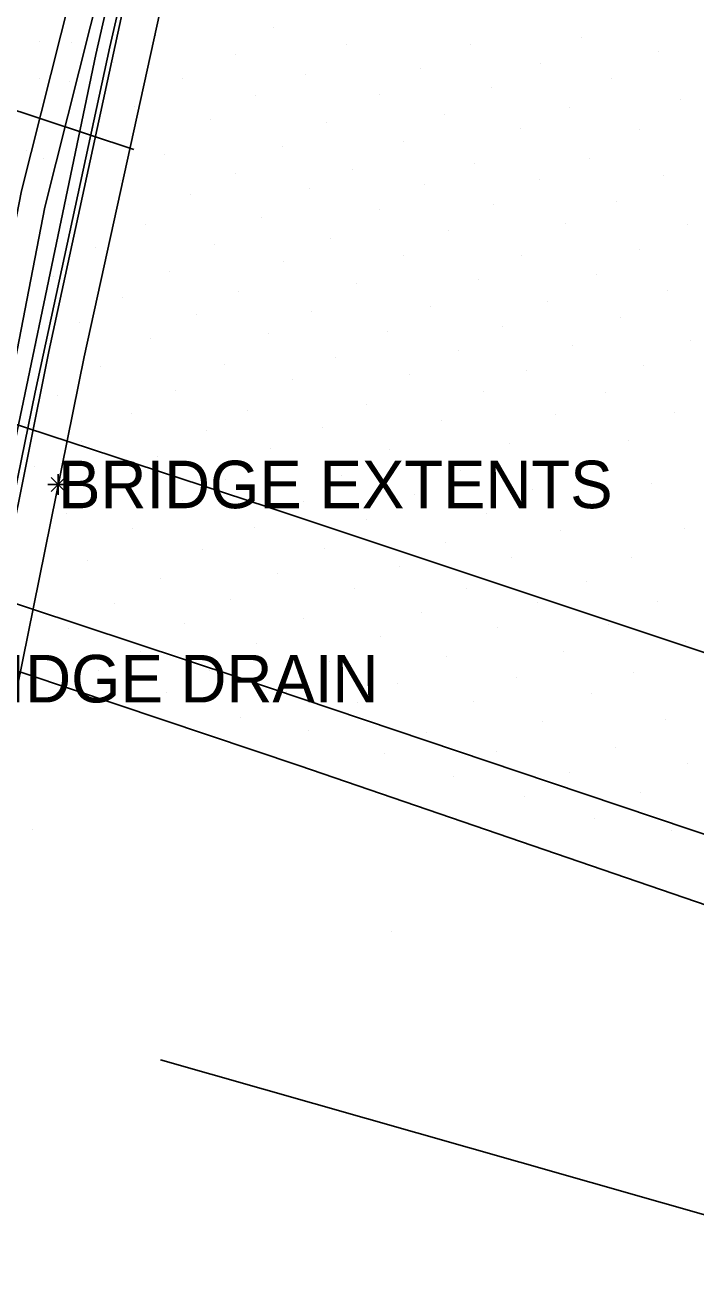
# Model space of a CAD drawing. Extents: x 1733582 to 1734070, y 467256 to 468256.
# Drawn here: x 1733868.45 to 1733893.84, y 467736.94 to 467784.83 of the extents above; entities that cross this region are included whole.
import ezdxf

# ---------------------------------------------------------------- set-up
doc = ezdxf.new("R2010")
doc.units = 0
for name, color, linetype in [('Default', 7, 'Continuous'), ('S_Bridge_Curb', 7, 'Continuous'), ('S_Bridge_Deck', 7, 'Continuous'), ('S_Bridge_Rail', 7, 'Continuous'), ('S_Ground_LevelString', 7, 'Continuous'), ('S_Ground_SpotElevation', 7, 'Continuous'), ('S_Guardrail_Beam', 7, 'Continuous'), ('S_Misc_MiscFeature', 7, 'Continuous'), ('S_Misc_MiscItems', 7, 'Continuous'), ('S_Roadway_Edge_Pavement', 7, 'Continuous'), ('S_Roadway_Painted_Lines', 7, 'Continuous'), ('S_Text', 7, 'Continuous')]:
    doc.layers.add(name, color=color, linetype=linetype)

# ---------------------------------------------------------------- blocks, each defined once
blk = doc.blocks.new('POINT_DISPLAY')
at = {"layer": 'Default'}
blk.add_line((0, 0), (0, 0), dxfattribs=at)

msp = doc.modelspace()

# ---------------------------------------------------------------- linework, layer by layer
at = {"layer": 'S_Bridge_Curb'}
msp.add_lwpolyline([(1733850.525, 467652.736), (1733851.676, 467663.636), (1733852.883, 467674.082), (1733854.262, 467685.548), (1733855.565, 467694.75), (1733856.845, 467703.748), (1733858.974, 467717.399), (1733861.233, 467731.524), (1733863.482, 467743.881), (1733865.283, 467752.922), (1733867.113, 467762.582), (1733868.83, 467770.933), (1733871.654, 467784.015), (1733874.05, 467794.414), (1733876.107, 467803.265), (1733877.952, 467810.863), (1733879.709, 467817.89), (1733881.379, 467824.23), (1733883.522, 467832.303), (1733885.6, 467839.734), (1733886.897, 467844.023)], dxfattribs=at)
at = {"layer": 'S_Bridge_Deck'}
msp.add_lwpolyline([(1733886.549, 467844.629), (1733884.683, 467838.178), (1733882.551, 467830.444), (1733878.067, 467813.135), (1733874.221, 467797.292), (1733871.125, 467783.729), (1733866.753, 467762.871), (1733863.994, 467749.165), (1733860.716, 467731.07), (1733858.373, 467716.77), (1733855.935, 467700.728), (1733853.766, 467684.771), (1733851.796, 467669.015), (1733850.46, 467656.5), (1733850.135, 467652.683), (1733850.236, 467652.213)], dxfattribs=at)
at = {"layer": 'S_Bridge_Rail'}
msp.add_lwpolyline([(1733886.303, 467841.899), (1733884.339, 467834.722), (1733880.236, 467819.247), (1733876.383, 467803.848), (1733872.741, 467788.157), (1733869.344, 467772.479), (1733866.194, 467756.807), (1733863.147, 467741.167), (1733860.402, 467725.353), (1733857.873, 467709.488), (1733855.573, 467693.7), (1733853.508, 467677.718), (1733851.616, 467661.907), (1733850.883, 467654.795)], dxfattribs=at)
at = {"layer": 'S_Ground_LevelString'}
msp.add_lwpolyline([(1733873.58, 467745.647), (1733887.182, 467741.776), (1733900.784, 467737.904), (1733914.385, 467734.032), (1733927.987, 467730.16)], dxfattribs=at)
at = {"layer": 'S_Guardrail_Beam'}
msp.add_lwpolyline([(1733971.13, 467727.753), (1733959.189, 467731.849), (1733947.467, 467735.892), (1733935.587, 467740.11), (1733923.652, 467744.12), (1733911.999, 467748.09), (1733900.23, 467752.154), (1733888.348, 467756.158), (1733876.584, 467760.123), (1733864.636, 467764.075), (1733852.71, 467768.12), (1733840.864, 467771.985), (1733828.96, 467775.911), (1733821.157, 467778.362), (1733811.276, 467781.779), (1733806.138, 467783.487), (1733804.067, 467784.255), (1733803.797, 467784.235), (1733803.622, 467784.139), (1733803.485, 467783.985), (1733803.422, 467783.75), (1733803.437, 467783.569), (1733803.561, 467783.396)], dxfattribs=at)
at = {"layer": 'S_Misc_MiscFeature'}
for points in [[(1733848.559, 467652.836), (1733852.024, 467679.791), (1733855.066, 467703.463), (1733857.598, 467722.922), (1733860.883, 467740.131), (1733863.02, 467751.281), (1733865.314, 467763.253), (1733868.31, 467778.566), (1733873.148, 467797.76), (1733879.142, 467821.53), (1733885.249, 467845.685)], [(1733849.555, 467652.651), (1733852.726, 467677.347), (1733855.925, 467702.233), (1733858.601, 467722.747), (1733863.855, 467750.228), (1733866.106, 467762.026), (1733869.19, 467777.948), (1733873.963, 467796.905), (1733880.016, 467820.978), (1733886.27, 467845.573)], [(1733887.367, 467840.604), (1733883.605, 467826.737), (1733879.636, 467811.346), (1733877.727, 467803.516), (1733874.188, 467788.265), (1733870.678, 467772.276), (1733867.49, 467756.558), (1733864.467, 467740.84), (1733861.741, 467725.141), (1733859.155, 467709.272), (1733856.917, 467693.32), (1733854.838, 467677.445), (1733853.015, 467661.799), (1733852.333, 467655.629)]]:
    msp.add_lwpolyline(points, dxfattribs=at)
at = {"layer": 'S_Misc_MiscItems'}
for p, q in [((1733869.698, 467767.836), (1733869.698, 467767.05)), ((1733870.091, 467767.443), (1733869.305, 467767.443)), ((1733869.96, 467767.181), (1733869.436, 467767.705)), ((1733869.96, 467767.705), (1733869.436, 467767.181))]:
    msp.add_line(p, q, dxfattribs=at)
at = {"layer": 'S_Roadway_Edge_Pavement'}
msp.add_lwpolyline([(1733611.876, 467844.635), (1733674.83, 467825.942), (1733744.192, 467804.366), (1733759.494, 467799.192), (1733788.268, 467787.576), (1733794.963, 467784.321), (1733814.735, 467777.995), (1733835.64, 467771.291), (1733878.809, 467756.802), (1733915.97, 467744.059), (1733950.334, 467732.351), (1733979.802, 467721.488), (1733993.679, 467716.295), (1734030.704, 467703.141), (1734054.753, 467695.101)], dxfattribs=at)
at = {"layer": 'S_Roadway_Painted_Lines'}
msp.add_line((1733858.283, 467784.833), (1733872.566, 467780.13), dxfattribs=at)
msp.add_lwpolyline([(1733613.543, 467849.189), (1733648.882, 467838.819), (1733697.382, 467824.233), (1733741.485, 467810.479), (1733805.714, 467790.022), (1733833.501, 467781.081), (1733877.654, 467766.584), (1733913.643, 467754.586), (1734001.896, 467724.119), (1734057.373, 467704.28)], dxfattribs=at)

# ---------------------------------------------------------------- block references
at = {"layer": 'S_Ground_SpotElevation'}
for p in [(1733877.846, 467784.741), (1733868.977, 467784.207), (1733870.201, 467784.169), (1733873.395, 467784.465), (1733880.602, 467784.106), (1733885.303, 467784.109), (1733889.502, 467784.366), (1733876.412, 467783.723), (1733892.432, 467783.856), (1733871.784, 467783.418), (1733883.412, 467783.203), (1733887.959, 467783.396), (1733868.992, 467782.822), (1733870.115, 467782.689), (1733874.399, 467782.811), (1733879.05, 467782.973), (1733890.646, 467782.835), (1733877.175, 467782.181), (1733881.877, 467782.209), (1733886.126, 467782.491), (1733872.594, 467781.776), (1733889.069, 467781.715), (1733893.249, 467782.024), (1733875.486, 467781.249), (1733879.856, 467781.161), (1733884.322, 467781.45), (1733871.036, 467780.959), (1733887.203, 467780.91), (1733891.704, 467780.901), (1733878.201, 467780.254), (1733882.774, 467780.444), (1733868.513, 467780.104), (1733869.137, 467779.805), (1733873.734, 467779.936), (1733889.823, 467779.8), (1733880.847, 467779.384), (1733885.473, 467779.603), (1733872.042, 467778.964), (1733876.404, 467779.216), (1733883.575, 467778.82), (1733887.935, 467779.008), (1733892.611, 467779.157), (1733874.693, 467778.411), (1733879.202, 467778.643), (1733870.086, 467778.049), (1733881.878, 467777.863), (1733886.199, 467778.035), (1733890.833, 467778.145), (1733877.394, 467777.547), (1733888.93, 467777.329), (1733873.023, 467777.279), (1733884.472, 467777.071), (1733893.518, 467777.284), (1733871.096, 467776.42), (1733875.634, 467776.513), (1733880.027, 467776.772), (1733878.252, 467775.904), (1733882.764, 467776.097), (1733887.262, 467776.113), (1733891.731, 467776.347), (1733873.914, 467775.505), (1733869.504, 467775.336), (1733880.979, 467775.047), (1733885.603, 467775.193), (1733890.07, 467775.402), (1733872.131, 467774.54), (1733876.546, 467774.752), (1733892.794, 467774.8), (1733879.291, 467773.976), (1733883.783, 467774.188), (1733888.223, 467774.385), (1733870.519, 467773.59), (1733874.938, 467773.877), (1733890.981, 467773.749), (1733877.659, 467773.146), (1733882.162, 467773.219), (1733886.514, 467773.426), (1733868.891, 467772.69), (1733873.188, 467772.968), (1733889.16, 467772.69), (1733893.629, 467772.877), (1733880.209, 467772.267), (1733884.863, 467772.502), (1733871.292, 467771.918), (1733875.988, 467771.991), (1733883.02, 467771.621), (1733887.429, 467771.776), (1733891.867, 467771.965), (1733878.561, 467771.432), (1733869.685, 467770.795), (1733874.161, 467770.992), (1733885.793, 467770.945), (1733890.412, 467770.944), (1733872.492, 467770.135), (1733876.854, 467770.237), (1733881.389, 467770.482), (1733893.049, 467770.153), (1733884.207, 467769.851), (1733888.529, 467770.095), (1733875.301, 467769.475), (1733879.704, 467769.618), (1733870.583, 467769.08), (1733877.731, 467768.802), (1733882.246, 467768.753), (1733886.797, 467769.003), (1733891.287, 467769.125), (1733873.475, 467768.495), (1733868.786, 467768.111), (1733880.441, 467767.773), (1733884.933, 467767.99), (1733889.417, 467768.191), (1733871.624, 467767.487), (1733876.045, 467767.621), (1733892.157, 467767.498), (1733874.425, 467766.822), (1733878.984, 467766.798), (1733883.185, 467767.065), (1733887.645, 467767.245), (1733869.997, 467766.347), (1733885.902, 467766.326), (1733890.344, 467766.515), (1733881.386, 467766.1), (1733872.524, 467765.762), (1733877.145, 467765.797), (1733888.725, 467765.699), (1733893.415, 467765.785), (1733875.178, 467764.989), (1733879.777, 467764.999), (1733884.35, 467765.261), (1733870.829, 467764.57), (1733886.851, 467764.662), (1733891.424, 467764.668), (1733878.004, 467764.052), (1733882.613, 467764.344), (1733868.995, 467763.852), (1733873.573, 467763.869), (1733880.937, 467763.503), (1733885.18, 467763.502), (1733889.712, 467763.773), (1733876.221, 467763.101), (1733887.86, 467762.991), (1733892.399, 467763), (1733871.824, 467762.943), (1733883.461, 467762.609), (1733874.481, 467762.167), (1733878.976, 467762.382), (1733886.338, 467762.029), (1733890.543, 467762.143), (1733870.099, 467761.981), (1733881.914, 467761.672), (1733872.814, 467761.111), (1733877.204, 467761.429), (1733888.852, 467761.128), (1733893.443, 467761.478), (1733879.989, 467760.756), (1733884.389, 467760.925), (1733871.224, 467760.405), (1733875.419, 467760.398), (1733887.038, 467760.14), (1733891.502, 467760.317), (1733882.56, 467759.923), (1733873.797, 467759.554), (1733878.355, 467759.598), (1733881.038, 467759.168), (1733885.437, 467759.21), (1733889.912, 467759.523), (1733876.587, 467758.618), (1733888.027, 467758.472), (1733892.683, 467758.528), (1733879.163, 467758.14), (1733883.652, 467758.051), (1733882.074, 467757.241), (1733886.296, 467757.347), (1733890.818, 467757.488), (1733893.534, 467756.88), (1733884.655, 467756.372), (1733889.046, 467756.532), (1733891.76, 467755.788), (1733887.364, 467755.643), (1733868.715, 467754.384), (1733890.007, 467754.806), (1733892.945, 467754.342), (1733882.317, 467750.512), (1733873.58, 467745.647), (1733887.182, 467741.776)]:
    msp.add_blockref('POINT_DISPLAY', p, dxfattribs=at)

# ---------------------------------------------------------------- texts
at = {"layer": 'S_Text'}
for s, p in [('BRIDGE EXTENTS', (1733869.698, 467766.543)), ('BRIDGE DRAIN', (1733864.439, 467759.187))]:
    msp.add_text(s, height=1.8, dxfattribs=at).set_placement(p)

doc.saveas('drawing.dxf')
